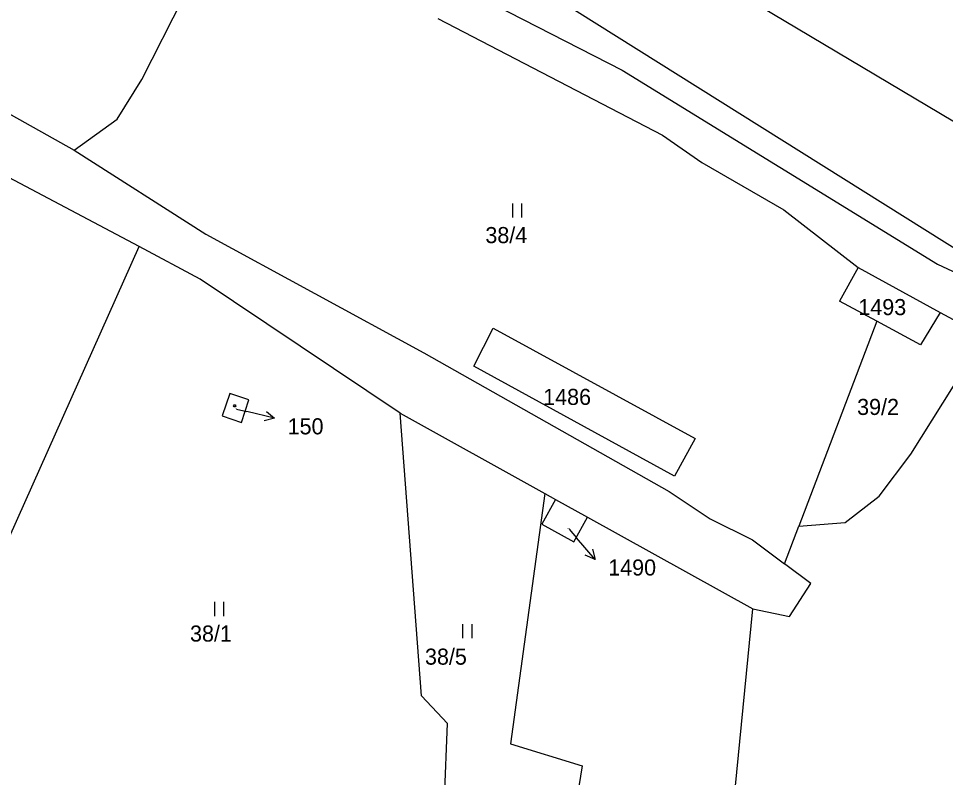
# Model space of a CAD drawing. Extents: x -850689 to -847910, y -1058374 to -1054747.
# Drawn here: x -849424.1 to -849326.1, y -1056175.1 to -1056094.9 of the extents above; entities that cross this region are included whole.
import ezdxf

# ---------------------------------------------------------------- set-up
doc = ezdxf.new("R2010")
doc.units = 0
for name, color, linetype in [('KN_HRANICE', 7, 'Continuous'), ('KN_KULTURY', 7, 'Continuous'), ('KN_PARCELY', 7, 'Continuous')]:
    doc.layers.add(name, color=color, linetype=linetype)

# ---------------------------------------------------------------- blocks, each defined once
blk = doc.blocks.new('306')
for p, q in [((-0.5, 1.5), (-0.5, 0)), ((0.5, 0), (0.5, 1.5))]:
    blk.add_line(p, q)
blk = doc.blocks.new('NAHRADNI_SYMBOL')
blk.add_lwpolyline([(0.09, 0.15), (0.18, 0), (0.09, -0.15), (-0.09, -0.15), (-0.18, 0), (-0.09, 0.15), (0.09, 0.15)])
blk = doc.blocks.new('10292')
blk.add_line((0, 3), (0, 0))
blk.add_lwpolyline([(-0.5, 2), (0, 3), (0.5, 2)])

msp = doc.modelspace()

# ---------------------------------------------------------------- linework, layer by layer
at = {"layer": 'KN_HRANICE'}
for p, q in [((-849447.97, -1056042.09), (-849309.42, -1056129.11)), ((-849411.05, -1056101.37), (-849402.23, -1056083.97)), ((-849382.48, -1056088.99), (-849360.29, -1056100.39)), ((-849350.5, -1056090.75), (-849292.1, -1056125.54)), ((-849443.99, -1056094.41), (-849418.2, -1056108.82)), ((-849379.78, -1056094.91), (-849356.05, -1056107.25)), ((-849360.29, -1056100.39), (-849326.99, -1056120.89)), ((-849411.33, -1056119.03), (-849445.63, -1056100.85)), ((-849413.64, -1056105.56), (-849411.05, -1056101.37)), ((-849418.2, -1056108.82), (-849413.64, -1056105.56)), ((-849356.05, -1056107.25), (-849351.87, -1056110.15)), ((-849418.2, -1056108.82), (-849404.3, -1056117.7)), ((-849351.87, -1056110.15), (-849343.23, -1056115.14)), ((-849343.23, -1056115.14), (-849335.37, -1056121.22)), ((-849404.3, -1056117.7), (-849381.24, -1056130.24)), ((-849425.04, -1056149.71), (-849411.33, -1056119.03)), ((-849404.87, -1056122.47), (-849411.33, -1056119.03)), ((-849326.99, -1056120.89), (-849309.42, -1056129.11)), ((-849335.37, -1056121.22), (-849337.34, -1056124.78)), ((-849335.37, -1056121.22), (-849326.68, -1056125.99)), ((-849383.75, -1056136.63), (-849404.87, -1056122.47)), ((-849333.4, -1056126.91), (-849337.34, -1056124.78)), ((-849333.4, -1056126.91), (-849341.62, -1056148.56)), ((-849328.77, -1056129.41), (-849333.4, -1056126.91)), ((-849326.68, -1056125.99), (-849328.77, -1056129.41)), ((-849326.68, -1056125.99), (-849322, -1056128.52)), ((-849375.98, -1056131.66), (-849373.93, -1056127.66)), ((-849373.93, -1056127.66), (-849352.58, -1056139.31)), ((-849381.24, -1056130.24), (-849355.34, -1056144.91)), ((-849354.75, -1056143.29), (-849375.98, -1056131.66)), ((-849329.78, -1056140.97), (-849324.16, -1056131.97)), ((-849401.75, -1056134.54), (-849402.56, -1056136.9)), ((-849399.74, -1056135.23), (-849401.75, -1056134.54)), ((-849400.53, -1056137.6), (-849399.74, -1056135.23)), ((-849381.49, -1056166.49), (-849383.75, -1056136.63)), ((-849383.75, -1056136.63), (-849368.45, -1056145.12)), ((-849402.56, -1056136.9), (-849400.53, -1056137.6)), ((-849352.58, -1056139.31), (-849354.75, -1056143.29)), ((-849333.15, -1056145.41), (-849329.78, -1056140.97)), ((-849368.45, -1056145.12), (-849372.11, -1056171.57)), ((-849368.45, -1056145.12), (-849367.33, -1056145.75)), ((-849355.34, -1056144.91), (-849351.01, -1056147.79)), ((-849336.73, -1056148.17), (-849333.15, -1056145.41)), ((-849367.33, -1056145.75), (-849368.78, -1056148.36)), ((-849367.33, -1056145.75), (-849363.95, -1056147.62)), ((-849368.78, -1056148.36), (-849365.39, -1056150.22)), ((-849365.39, -1056150.22), (-849363.95, -1056147.62)), ((-849363.95, -1056147.62), (-849346.5, -1056157.31)), ((-849351.01, -1056147.79), (-849346.52, -1056150.01)), ((-849341.62, -1056148.56), (-849336.73, -1056148.17)), ((-849343.13, -1056152.55), (-849341.62, -1056148.56)), ((-849346.52, -1056150.01), (-849343.13, -1056152.55)), ((-849340.35, -1056154.64), (-849343.13, -1056152.55)), ((-849342.62, -1056158.13), (-849340.35, -1056154.64)), ((-849348.36, -1056176.35), (-849346.5, -1056157.31)), ((-849346.5, -1056157.31), (-849342.62, -1056158.13)), ((-849378.74, -1056169.41), (-849381.49, -1056166.49)), ((-849379.32, -1056183.62), (-849378.74, -1056169.41)), ((-849372.11, -1056171.57), (-849364.51, -1056173.91)), ((-849364.51, -1056173.91), (-849366.23, -1056184.36))]:
    msp.add_line(p, q, dxfattribs=at)
at = {"layer": 'KN_PARCELY'}
for p, q in [((-849401.06, -1056136.2), (-849399.95, -1056136.47)), ((-849365.91, -1056148.88), (-849365.11, -1056149.81))]:
    msp.add_line(p, q, dxfattribs=at)

# ---------------------------------------------------------------- block references
at = {"layer": 'KN_KULTURY'}
for p in [(-849371.39, -1056115.96), (-849402.88, -1056158.07), (-849376.66, -1056160.42)]:
    msp.add_blockref('306', p, dxfattribs=at)
at = {"layer": 'KN_KULTURY', "xscale": 0.67, "yscale": 0.67}
msp.add_blockref('NAHRADNI_SYMBOL', (-849401.24, -1056135.85), dxfattribs=at)
at = {"layer": 'KN_PARCELY'}
for p, rotation in [((-849399.95, -1056136.47), -103.54409100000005), ((-849365.11, -1056149.81), -139.41124900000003)]:
    msp.add_blockref('10292', p, dxfattribs=dict(at, rotation=rotation))

# ---------------------------------------------------------------- texts
for s, height, p in [('38/4', 1.7, (-849374.75, -1056118.66)), ('1493', 1.7, (-849335.34, -1056126.27)), ('1486', 1.7, (-849368.64, -1056135.76)), ('39/2', 1.7, (-849335.469, -1056136.82)), ('150', 0.1, (-849401.21, -1056136.2)), ('150', 1.7, (-849395.64, -1056138.87)), ('1490', 0.1, (-849366.108, -1056148.88)), ('1490', 1.7, (-849361.77, -1056153.79)), ('38/1', 1.7, (-849405.956, -1056160.77)), ('38/5', 1.7, (-849381.129, -1056163.21))]:
    msp.add_text(s, height=height, dxfattribs=at).set_placement(p)

doc.saveas('drawing.dxf')
